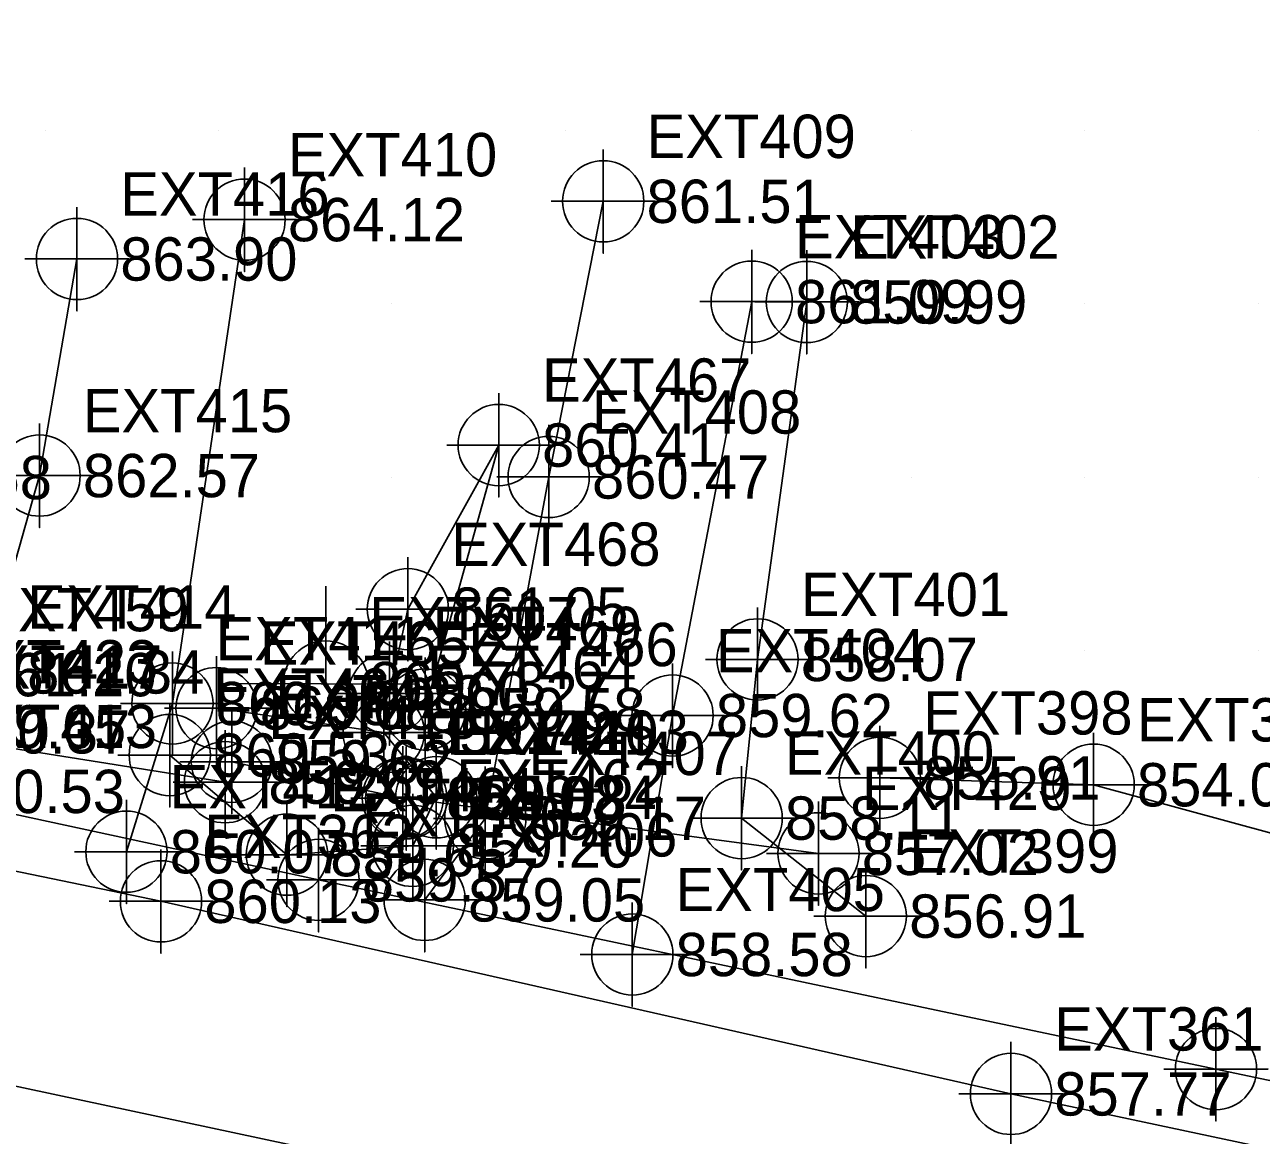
# Model space of a CAD drawing. Extents: x 1762120 to 1766775, y 709485 to 712965.
# Drawn here: x 1762678.8 to 1762750.2, y 712662 to 712726.1 of the extents above; entities that cross this region are included whole.
import ezdxf

# ---------------------------------------------------------------- set-up
doc = ezdxf.new("R2010")
doc.units = 0
for name, color, linetype in [('Exist DTM Breakline', 7, 'Continuous'), ('Exist DTM Breakline Cogo Elevation', 7, 'Continuous'), ('Exist DTM Breakline Cogo Number', 7, 'Continuous'), ('Exist DTM Breakline Cogo Point CELL', 7, 'Continuous'), ('Exist DTM Crownline', 7, 'Continuous'), ('Exist DTM Drainline', 7, 'Continuous'), ('Exist DTM Drainline Cogo Elevation', 7, 'Continuous'), ('Exist DTM Drainline Cogo Number', 7, 'Continuous'), ('Exist DTM Drainline Cogo Point CELL', 7, 'Continuous'), ('Exist DTM QL2 LIDAR Elevation Point', 7, 'Continuous'), ('Exist Roads EOP', 7, 'Continuous'), ('Exist Roads EOP Cogo Elevation', 7, 'Continuous'), ('Exist Roads EOP Cogo Number', 7, 'Continuous'), ('Exist Roads EOP Cogo Point CELL', 7, 'Continuous'), ('Exist Roads EOP Other', 7, 'Continuous'), ('Exist Roads EOP Other Cogo Elevation', 7, 'Continuous'), ('Exist Roads EOP Other Cogo Number', 7, 'Continuous'), ('Exist Roads EOP Other Cogo Point CELL', 7, 'Continuous'), ('Exist Structure Minor Pipes RCP 12 Inch', 7, 'Continuous'), ('Exist Structure Minor Pipes RCP 12 Inch Cogo Comment', 7, 'Continuous'), ('Exist Structure Minor Pipes RCP 12 Inch Cogo Number', 7, 'Continuous'), ('Exist Structure Minor Pipes RCP 12 Inch Cogo Point CELL', 7, 'Continuous'), ('Exist Utilities Gas UG Line SUE LOS C', 7, 'Continuous'), ('Exist Utilities Gas UG Line SUE LOS C Cogo Elevation', 7, 'Continuous'), ('Exist Utilities Gas UG Line SUE LOS C Cogo Number', 7, 'Continuous'), ('Exist Utilities Gas UG Line SUE LOS C Cogo Point CELL', 7, 'Continuous'), ('Exist Utilities Power Joint Use Telephone CELL', 7, 'Continuous'), ('Exist Utilities Power Joint Use Telephone Cogo Elevation', 7, 'Continuous'), ('Exist Utilities Power Joint Use Telephone Cogo Number', 7, 'Continuous')]:
    doc.layers.add(name, color=color, linetype=linetype)

msp = doc.modelspace()

# ---------------------------------------------------------------- linework, layer by layer
at = {"layer": 'Exist DTM Breakline'}
for points in [[(1762727.363, 712674.673), (1762720.192, 712680.329), (1762721.109, 712689.483), (1762723.954, 712710.11)], [(1762701.922, 712686.595), (1762706.173, 712701.854), (1762700.93, 712692.385), (1762699.862, 712687.525)], [(1762687.186, 712683.965), (1762693.949, 712678.216), (1762701.214, 712678.723), (1762702.565, 712681.53), (1762699.534, 712685.272), (1762689.887, 712686.676)]]:
    msp.add_lwpolyline(points, dxfattribs=at)
at = {"layer": 'Exist DTM Breakline Cogo Point CELL'}
for points in [[(1762723.954, 712713.11), (1762723.954, 712707.11), (1762723.954, 712710.11), (1762726.954, 712710.11), (1762720.954, 712710.11)], [(1762706.173, 712704.854), (1762706.173, 712698.854), (1762706.173, 712701.854), (1762709.173, 712701.854), (1762703.173, 712701.854)], [(1762700.93, 712695.385), (1762700.93, 712689.385), (1762700.93, 712692.385), (1762703.93, 712692.385), (1762697.93, 712692.385)], [(1762721.109, 712692.483), (1762721.109, 712686.483), (1762721.109, 712689.483), (1762724.109, 712689.483), (1762718.109, 712689.483)], [(1762699.862, 712690.525), (1762699.862, 712684.525), (1762699.862, 712687.525), (1762702.862, 712687.525), (1762696.862, 712687.525)], [(1762689.887, 712689.676), (1762689.887, 712683.676), (1762689.887, 712686.676), (1762692.887, 712686.676), (1762686.887, 712686.676)], [(1762701.922, 712689.595), (1762701.922, 712683.595), (1762701.922, 712686.595), (1762704.922, 712686.595), (1762698.922, 712686.595)], [(1762699.534, 712688.272), (1762699.534, 712682.272), (1762699.534, 712685.272), (1762702.534, 712685.272), (1762696.534, 712685.272)], [(1762687.186, 712686.965), (1762687.186, 712680.965), (1762687.186, 712683.965), (1762690.186, 712683.965), (1762684.186, 712683.965)], [(1762702.565, 712684.53), (1762702.565, 712678.53), (1762702.565, 712681.53), (1762705.565, 712681.53), (1762699.565, 712681.53)], [(1762720.192, 712683.329), (1762720.192, 712677.329), (1762720.192, 712680.329), (1762723.192, 712680.329), (1762717.192, 712680.329)], [(1762693.949, 712681.216), (1762693.949, 712675.216), (1762693.949, 712678.216), (1762696.949, 712678.216), (1762690.949, 712678.216)], [(1762701.214, 712681.723), (1762701.214, 712675.723), (1762701.214, 712678.723), (1762704.214, 712678.723), (1762698.214, 712678.723)], [(1762727.363, 712677.673), (1762727.363, 712671.673), (1762727.363, 712674.673), (1762730.363, 712674.673), (1762724.363, 712674.673)]]:
    msp.add_lwpolyline(points, dxfattribs=at)
for centre in [(1762723.954, 712710.11), (1762706.173, 712701.854), (1762700.93, 712692.385), (1762721.109, 712689.483), (1762699.862, 712687.525), (1762689.887, 712686.676), (1762701.922, 712686.595), (1762699.534, 712685.272), (1762687.186, 712683.965), (1762702.565, 712681.53), (1762720.192, 712680.329), (1762693.949, 712678.216), (1762701.214, 712678.723), (1762727.363, 712674.673)]:
    msp.add_circle(centre, 2.344, dxfattribs=at)
at = {"layer": 'Exist DTM Crownline'}
msp.add_lwpolyline([(1762166.547, 712774.687), (1762217.293, 712763.929), (1762266.928, 712753.164), (1762315.989, 712742.645), (1762361.304, 712733.127), (1762409.518, 712722.711), (1762461.505, 712711.505), (1762512.117, 712700.307), (1762561.004, 712689.861), (1762611.478, 712678.845), (1762663.765, 712667.96), (1762715.266, 712656.972), (1762767.733, 712645.753), (1762820.16, 712634.416), (1762873.558, 712623.116), (1762907.318, 712615.867), (1762954.844, 712607.608), (1762970.656, 712604.722)], dxfattribs=at)
at = {"layer": 'Exist DTM Drainline'}
msp.add_line((1762700.637, 712681.48), (1762690.767, 712683.578), dxfattribs=at)
msp.add_lwpolyline([(1762956.078, 712637.37), (1762926.008, 712644.157), (1762891.887, 712654.326), (1762866.923, 712662.338), (1762827.769, 712667.978), (1762778.648, 712676.423), (1762761.216, 712676.604), (1762740.508, 712682.253), (1762728.174, 712682.65)], dxfattribs=at)
at = {"layer": 'Exist DTM Drainline Cogo Point CELL'}
for points in [[(1762690.767, 712686.578), (1762690.767, 712680.578), (1762690.767, 712683.578), (1762693.767, 712683.578), (1762687.767, 712683.578)], [(1762728.174, 712685.65), (1762728.174, 712679.65), (1762728.174, 712682.65), (1762731.174, 712682.65), (1762725.174, 712682.65)], [(1762740.508, 712685.253), (1762740.508, 712679.253), (1762740.508, 712682.253), (1762743.508, 712682.253), (1762737.508, 712682.253)], [(1762700.637, 712684.48), (1762700.637, 712678.48), (1762700.637, 712681.48), (1762703.637, 712681.48), (1762697.637, 712681.48)]]:
    msp.add_lwpolyline(points, dxfattribs=at)
for centre in [(1762690.767, 712683.578), (1762728.174, 712682.65), (1762740.508, 712682.253), (1762700.637, 712681.48)]:
    msp.add_circle(centre, 2.344, dxfattribs=at)
at = {"layer": 'Exist DTM QL2 LIDAR Elevation Point'}
for p, q in [((1762680, 712720), (1762680, 712720)), ((1762690, 712720), (1762690, 712720)), ((1762700, 712720), (1762700, 712720)), ((1762710, 712720), (1762710, 712720)), ((1762720, 712720), (1762720, 712720)), ((1762730, 712720), (1762730, 712720)), ((1762740, 712720), (1762740, 712720)), ((1762750, 712720), (1762750, 712720)), ((1762700, 712710), (1762700, 712710)), ((1762730, 712710), (1762730, 712710)), ((1762740, 712710), (1762740, 712710)), ((1762750, 712710), (1762750, 712710)), ((1762700, 712700), (1762700, 712700)), ((1762730, 712700), (1762730, 712700)), ((1762740, 712700), (1762740, 712700)), ((1762750, 712700), (1762750, 712700)), ((1762730, 712690), (1762730, 712690)), ((1762740, 712690), (1762740, 712690)), ((1762750, 712690), (1762750, 712690))]:
    msp.add_line(p, q, dxfattribs=at)
at = {"layer": 'Exist Roads EOP'}
msp.add_lwpolyline([(1762972.643, 712616.327), (1762930.479, 712622.907), (1762881.99, 712633.196), (1762831.971, 712644.063), (1762782.816, 712654.409), (1762735.737, 712664.412), (1762686.68, 712675.525), (1762639.564, 712685.265), (1762589.399, 712696.151), (1762546.232, 712705.49), (1762496.404, 712716.081), (1762446.151, 712726.895), (1762396.234, 712737.694), (1762346.428, 712748.231), (1762295.972, 712759.182), (1762245.105, 712770.099), (1762193.683, 712780.972), (1762169.004, 712786.417)], dxfattribs=at)
at = {"layer": 'Exist Roads EOP Cogo Point CELL'}
for points in [[(1762686.68, 712678.525), (1762686.68, 712672.525), (1762686.68, 712675.525), (1762689.68, 712675.525), (1762683.68, 712675.525)], [(1762735.737, 712667.412), (1762735.737, 712661.412), (1762735.737, 712664.412), (1762738.737, 712664.412), (1762732.737, 712664.412)]]:
    msp.add_lwpolyline(points, dxfattribs=at)
for centre in [(1762686.68, 712675.525), (1762735.737, 712664.412)]:
    msp.add_circle(centre, 2.344, dxfattribs=at)
at = {"layer": 'Exist Roads EOP Other'}
for points in [[(1762701.9, 712675.608), (1762705.399, 712680.312), (1762709.056, 712700.012), (1762712.206, 712715.919)], [(1762691.505, 712714.863), (1762687.339, 712686.939), (1762684.685, 712678.389)], [(1762671.874, 712681.868), (1762676.456, 712688.763), (1762679.673, 712700.094), (1762681.831, 712712.591)], [(1762720.774, 712710.129), (1762716.206, 712686.246), (1762713.882, 712672.458)]]:
    msp.add_lwpolyline(points, dxfattribs=at)
at = {"layer": 'Exist Roads EOP Other Cogo Point CELL'}
for points in [[(1762712.206, 712718.919), (1762712.206, 712712.919), (1762712.206, 712715.919), (1762715.206, 712715.919), (1762709.206, 712715.919)], [(1762691.505, 712717.863), (1762691.505, 712711.863), (1762691.505, 712714.863), (1762694.505, 712714.863), (1762688.505, 712714.863)], [(1762681.831, 712715.591), (1762681.831, 712709.591), (1762681.831, 712712.591), (1762684.831, 712712.591), (1762678.831, 712712.591)], [(1762720.774, 712713.129), (1762720.774, 712707.129), (1762720.774, 712710.129), (1762723.774, 712710.129), (1762717.774, 712710.129)], [(1762679.673, 712703.094), (1762679.673, 712697.094), (1762679.673, 712700.094), (1762682.673, 712700.094), (1762676.673, 712700.094)], [(1762709.056, 712703.012), (1762709.056, 712697.012), (1762709.056, 712700.012), (1762712.056, 712700.012), (1762706.056, 712700.012)], [(1762676.456, 712691.763), (1762676.456, 712685.763), (1762676.456, 712688.763), (1762679.456, 712688.763), (1762673.456, 712688.763)], [(1762687.339, 712689.939), (1762687.339, 712683.939), (1762687.339, 712686.939), (1762690.339, 712686.939), (1762684.339, 712686.939)], [(1762716.206, 712689.246), (1762716.206, 712683.246), (1762716.206, 712686.246), (1762719.206, 712686.246), (1762713.206, 712686.246)], [(1762705.399, 712683.312), (1762705.399, 712677.312), (1762705.399, 712680.312), (1762708.399, 712680.312), (1762702.399, 712680.312)], [(1762684.685, 712681.389), (1762684.685, 712675.389), (1762684.685, 712678.389), (1762687.685, 712678.389), (1762681.685, 712678.389)], [(1762701.9, 712678.608), (1762701.9, 712672.608), (1762701.9, 712675.608), (1762704.9, 712675.608), (1762698.9, 712675.608)], [(1762713.882, 712675.458), (1762713.882, 712669.458), (1762713.882, 712672.458), (1762716.882, 712672.458), (1762710.882, 712672.458)]]:
    msp.add_lwpolyline(points, dxfattribs=at)
for centre in [(1762712.206, 712715.919), (1762691.505, 712714.863), (1762681.831, 712712.591), (1762720.774, 712710.129), (1762679.673, 712700.094), (1762709.056, 712700.012), (1762687.339, 712686.939), (1762716.206, 712686.246), (1762705.399, 712680.312), (1762684.685, 712678.389), (1762701.9, 712675.608), (1762713.882, 712672.458)]:
    msp.add_circle(centre, 2.344, dxfattribs=at)
at = {"layer": 'Exist Structure Minor Pipes RCP 12 Inch'}
for p, q in [((1762672.176, 712685.305), (1762690.378, 712682.399)), ((1762700.836, 712681.469), (1762724.628, 712678.292))]:
    msp.add_line(p, q, dxfattribs=at)
at = {"layer": 'Exist Structure Minor Pipes RCP 12 Inch Cogo Point CELL'}
for points in [[(1762690.378, 712685.399), (1762690.378, 712679.399), (1762690.378, 712682.399), (1762693.378, 712682.399), (1762687.378, 712682.399)], [(1762700.836, 712684.469), (1762700.836, 712678.469), (1762700.836, 712681.469), (1762703.836, 712681.469), (1762697.836, 712681.469)], [(1762724.628, 712681.292), (1762724.628, 712675.292), (1762724.628, 712678.292), (1762727.628, 712678.292), (1762721.628, 712678.292)]]:
    msp.add_lwpolyline(points, dxfattribs=at)
for centre in [(1762690.378, 712682.399), (1762700.836, 712681.469), (1762724.628, 712678.292)]:
    msp.add_circle(centre, 2.344, dxfattribs=at)
at = {"layer": 'Exist Utilities Gas UG Line SUE LOS C'}
msp.add_lwpolyline([(1762186.211, 712786.583), (1762241.953, 712774.527), (1762368.977, 712745.664), (1762446.664, 712730.32), (1762499.183, 712718.668), (1762560.329, 712705.064), (1762614.265, 712693.34), (1762654.566, 712685.659), (1762695.772, 712676.761), (1762747.569, 712665.846), (1762826.119, 712649.314), (1762887.977, 712636.743)], dxfattribs=at)
at = {"layer": 'Exist Utilities Gas UG Line SUE LOS C Cogo Point CELL'}
for points in [[(1762695.772, 712679.761), (1762695.772, 712673.761), (1762695.772, 712676.761), (1762698.772, 712676.761), (1762692.772, 712676.761)], [(1762747.569, 712668.846), (1762747.569, 712662.846), (1762747.569, 712665.846), (1762750.569, 712665.846), (1762744.569, 712665.846)]]:
    msp.add_lwpolyline(points, dxfattribs=at)
for centre in [(1762695.772, 712676.761), (1762747.569, 712665.846)]:
    msp.add_circle(centre, 2.344, dxfattribs=at)
at = {"layer": 'Exist Utilities Power Joint Use Telephone CELL'}
msp.add_line((1762696.193, 712688.092), (1762696.193, 712688.092), dxfattribs=at)
msp.add_lwpolyline([(1762690.255, 712688.092), (1762701.593, 712688.054), (1762696.193, 712688.072), (1762696.193, 712693.717)], dxfattribs=at)
msp.add_circle((1762696.194, 712688.098), 2.45, dxfattribs=at)

# ---------------------------------------------------------------- texts
at = {"layer": 'Exist DTM Breakline Cogo Elevation'}
for s, p in [('859.99', (1762726.454, 712708.86)), ('860.41', (1762708.673, 712700.604)), ('861.05', (1762703.43, 712691.135)), ('858.07', (1762723.609, 712688.233)), ('861.20', (1762676.2, 712687.357)), ('860.27', (1762702.362, 712686.275)), ('860.68', (1762692.387, 712685.426)), ('859.58', (1762704.422, 712685.345)), ('859.79', (1762702.034, 712684.022)), ('860.53', (1762689.686, 712682.715)), ('859.24', (1762705.065, 712680.28)), ('858.11', (1762722.692, 712679.079)), ('859.20', (1762703.714, 712677.473)), ('859.65', (1762696.449, 712676.966)), ('856.91', (1762729.863, 712673.423))]:
    msp.add_text(s, height=2.5, dxfattribs=at).set_placement(p)
at = {"layer": 'Exist DTM Breakline Cogo Number'}
for s, p in [('EXT402', (1762726.454, 712712.61)), ('EXT467', (1762708.673, 712704.354)), ('EXT458', (1762668.306, 712698.73)), ('EXT468', (1762703.43, 712694.885)), ('EXT401', (1762723.609, 712691.983)), ('EXT459', (1762676.2, 712691.107)), ('EXT469', (1762702.362, 712690.025)), ('EXT465', (1762692.387, 712689.176)), ('EXT466', (1762704.422, 712689.095)), ('EXT464', (1762702.034, 712687.772)), ('EXT460', (1762689.686, 712686.465)), ('EXT463', (1762705.065, 712684.03)), ('EXT400', (1762722.692, 712682.829)), ('EXT462', (1762703.714, 712681.223)), ('EXT461', (1762696.449, 712680.716)), ('EXT399', (1762729.863, 712677.173))]:
    msp.add_text(s, height=2.5, dxfattribs=at).set_placement(p)
at = {"layer": 'Exist DTM Drainline Cogo Elevation'}
for s, p in [('859.65', (1762674.446, 712684.348)), ('859.62', (1762693.267, 712682.328)), ('855.91', (1762730.674, 712681.4)), ('854.08', (1762743.008, 712681.003)), ('858.03', (1762703.137, 712680.23))]:
    msp.add_text(s, height=2.5, dxfattribs=at).set_placement(p)
at = {"layer": 'Exist DTM Drainline Cogo Number'}
for s, p in [('EXT423', (1762674.446, 712688.098)), ('EXT422', (1762693.267, 712686.078)), ('EXT398', (1762730.674, 712685.15)), ('EXT397', (1762743.008, 712684.753)), ('EXT421', (1762703.137, 712683.98))]:
    msp.add_text(s, height=2.5, dxfattribs=at).set_placement(p)
at = {"layer": 'Exist Roads EOP Cogo Elevation'}
for s, p in [('860.13', (1762689.18, 712674.275)), ('857.77', (1762738.237, 712663.162))]:
    msp.add_text(s, height=2.5, dxfattribs=at).set_placement(p)
at = {"layer": 'Exist Roads EOP Cogo Number'}
for s, p in [('EXT362', (1762689.18, 712678.025)), ('EXT361', (1762738.237, 712666.912))]:
    msp.add_text(s, height=2.5, dxfattribs=at).set_placement(p)
at = {"layer": 'Exist Roads EOP Other Cogo Elevation'}
for s, p in [('861.51', (1762714.706, 712714.669)), ('864.12', (1762694.005, 712713.613)), ('863.90', (1762684.331, 712711.341)), ('861.09', (1762723.274, 712708.879)), ('862.57', (1762682.173, 712698.844)), ('860.47', (1762711.556, 712698.762)), ('861.34', (1762678.956, 712687.513)), ('860.98', (1762689.839, 712685.689)), ('859.62', (1762718.706, 712684.996)), ('860.53', (1762674.374, 712680.618)), ('859.17', (1762707.899, 712679.062)), ('860.07', (1762687.185, 712677.139)), ('859.05', (1762704.4, 712674.358)), ('858.58', (1762716.382, 712671.208))]:
    msp.add_text(s, height=2.5, dxfattribs=at).set_placement(p)
at = {"layer": 'Exist Roads EOP Other Cogo Number'}
for s, p in [('EXT409', (1762714.706, 712718.419)), ('EXT410', (1762694.005, 712717.363)), ('EXT416', (1762684.331, 712715.091)), ('EXT403', (1762723.274, 712712.629)), ('EXT415', (1762682.173, 712702.594)), ('EXT408', (1762711.556, 712702.512)), ('EXT414', (1762678.956, 712691.263)), ('EXT411', (1762689.839, 712689.439)), ('EXT404', (1762718.706, 712688.746)), ('EXT413', (1762674.374, 712684.368)), ('EXT407', (1762707.899, 712682.812)), ('EXT412', (1762687.185, 712680.889)), ('EXT406', (1762704.4, 712678.108)), ('EXT405', (1762716.382, 712674.958))]:
    msp.add_text(s, height=2.5, dxfattribs=at).set_placement(p)
at = {"layer": 'Exist Structure Minor Pipes RCP 12 Inch Cogo Comment'}
for s, p in [('860.37', (1762674.676, 712684.055)), ('859.69', (1762692.878, 712681.149)), ('859.08', (1762703.336, 712680.219)), ('857.02', (1762727.128, 712677.042))]:
    msp.add_text(s, height=2.5, dxfattribs=at).set_placement(p)
at = {"layer": 'Exist Structure Minor Pipes RCP 12 Inch Cogo Number'}
for s, p in [('EXT417', (1762674.676, 712687.805)), ('EXT418', (1762692.878, 712684.899)), ('EXT419', (1762703.336, 712683.969)), ('EXT420', (1762727.128, 712680.792))]:
    msp.add_text(s, height=2.5, dxfattribs=at).set_placement(p)
at = {"layer": 'Exist Utilities Gas UG Line SUE LOS C Cogo Elevation'}
msp.add_text('859.57', height=2.5, dxfattribs=at).set_placement((1762698.272, 712675.511))
at = {"layer": 'Exist Utilities Gas UG Line SUE LOS C Cogo Number'}
msp.add_text('EXT506', height=2.5, dxfattribs=at).set_placement((1762698.272, 712679.261))
at = {"layer": 'Exist Utilities Power Joint Use Telephone Cogo Elevation'}
msp.add_text('860.73', height=2.5, dxfattribs=at).set_placement((1762698.693, 712686.842))
at = {"layer": 'Exist Utilities Power Joint Use Telephone Cogo Number'}
msp.add_text('EXT507', height=2.5, dxfattribs=at).set_placement((1762698.693, 712690.592))

doc.saveas('drawing.dxf')
